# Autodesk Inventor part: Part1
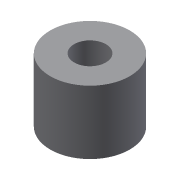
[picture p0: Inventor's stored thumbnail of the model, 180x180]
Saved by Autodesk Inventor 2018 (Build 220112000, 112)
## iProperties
Shininess: 77.0
Angle Display Precision: 2
Document Length Units: 11269
Document Angle Units: 11279
Document Time Units: 11290
Document Mass Units: 11283
Document Length Units Precision: 3
Document Angle Units Precision: 2
Created: 2002-01
Part Number: Part1
Document SubType Name: Modeling
Designer: ***
Density: 1 g/cm^3
Material: Generic
Appearance: Default
Density: 0.0
Volumn: 0.0
Area: 0.0
PropertySet Name: Model Information
Control State: 0
Master: False
Checked Out: False
Author: ***
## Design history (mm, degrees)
sketch "Sketch1"
  geometry: C1 r 25 at (0, 0); C2 r 10 at (0, 0)
  constraints: 2 centre point, 1 coincident
  dimensions: "d0" = 50 diameter of C1; "d1" = 20 diameter of C2
extrude "Extrusion1" new body sketch "Sketch1" distance "d2" = 40; taper "d3" = 0 deg
body "Solid1"
